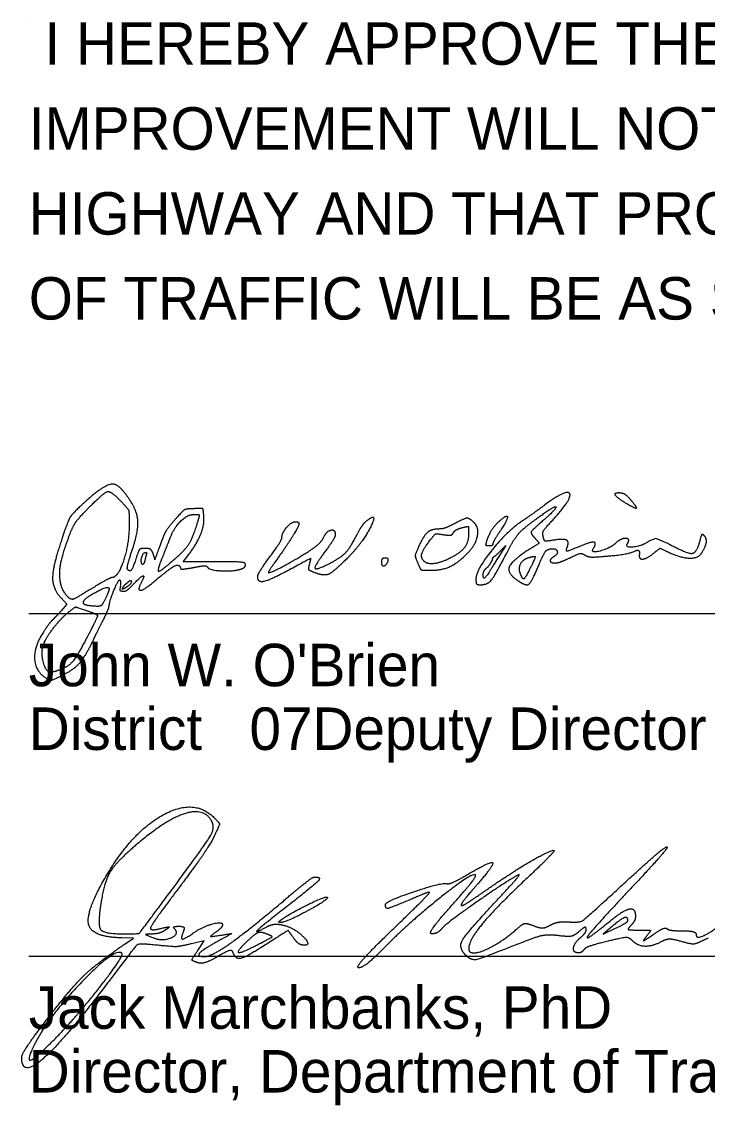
# Model space of a CAD drawing. Extents: x -31.7 to 34, y 0 to 22.
# Drawn here: x 24.504 to 26.767, y 7.305 to 10.877 of the extents above; entities that cross this region are included whole.
import ezdxf

# ---------------------------------------------------------------- set-up
doc = ezdxf.new("R2010")
doc.units = 0
doc.layers.add('SH_Data', color=7, linetype='Continuous')
doc.layers.add('SH_Text', color=7, linetype='Continuous')

msp = doc.modelspace()

# ---------------------------------------------------------------- linework, layer by layer
at = {"layer": 'SH_Data'}
for p, q in [((24.5279, 10.875), (24.5279, 10.875)), ((24.5279, 8.9262), (28.0279, 8.9262)), ((24.5279, 7.7968), (28.0279, 7.7968))]:
    msp.add_line(p, q, dxfattribs=at)
at = {"layer": 'SH_Text'}
for p, q in [((26.4932, 9.2925), (26.4932, 9.2925)), ((24.9902, 8.0019), (24.9902, 8.0019)), ((25.3555, 7.912), (25.3555, 7.912)), ((26.5045, 7.914), (26.5045, 7.914)), ((25.3107, 7.8703), (25.3107, 7.8703)), ((25.7273, 7.883), (25.7273, 7.883))]:
    msp.add_line(p, q, dxfattribs=at)
for points in [[(26.0685, 9.1173), (26.1019, 9.1505), (26.0672, 9.0956)], [(26.636, 9.1565), (26.597, 9.1731), (26.574, 9.1646)], [(25.1404, 9.0966), (25.0375, 9.0966), (25.0558, 9.1206)], [(24.6346, 8.9772), (24.654, 8.9566), (24.6346, 8.9348)], [(26.4527, 7.8943), (26.4232, 7.8687), (26.4638, 7.8884)], [(24.8425, 7.8349), (24.8732, 7.8561), (24.8354, 7.8568)], [(25.0855, 7.8151), (25.1067, 7.8474), (25.0649, 7.8373)]]:
    msp.add_lwpolyline(points, dxfattribs=at)
for points in [[(24.8676, 9.2902), (24.8304, 9.3511), (24.781, 9.3542), (24.7199, 9.2995)], [(24.7219, 9.2706), (24.7758, 9.3259), (24.8, 9.3304), (24.836, 9.2918)], [(26.2529, 9.2302), (26.3225, 9.305), (26.3023, 9.3379), (26.2232, 9.2785)], [(26.4932, 9.2925), (26.467, 9.3085), (26.4588, 9.3248), (26.4772, 9.3244)], [(26.4772, 9.3244), (26.4887, 9.3241), (26.5064, 9.3108), (26.5222, 9.2906)], [(24.7199, 9.2995), (24.6737, 9.2582), (24.656, 9.2292), (24.6319, 9.1557)], [(24.836, 9.2918), (24.8564, 9.2699), (24.8592, 9.261), (24.8592, 9.2177)], [(24.8663, 9.1257), (24.888, 9.1897), (24.8885, 9.2559), (24.8676, 9.2902)], [(26.5222, 9.2906), (26.5367, 9.2722), (26.5254, 9.2729), (26.4932, 9.2925)], [(24.6595, 9.1766), (24.672, 9.2107), (24.69, 9.2379), (24.7219, 9.2706)], [(25.0723, 9.2716), (25.0465, 9.2708), (25.0363, 9.2649), (25.0106, 9.2359)], [(25.1056, 9.2482), (25.1034, 9.271), (25.1012, 9.2725), (25.0723, 9.2716)], [(26.1167, 9.1474), (26.1337, 9.18), (26.1732, 9.218), (26.2332, 9.2597)], [(26.2232, 9.2785), (26.2012, 9.262), (26.1724, 9.2416), (26.1592, 9.2331)], [(26.2332, 9.2597), (26.2688, 9.2843), (26.2661, 9.2682), (26.2292, 9.2362)], [(24.8592, 9.2177), (24.8592, 9.1578), (24.8225, 9.0446), (24.803, 9.0446)], [(25.0106, 9.2359), (24.9936, 9.2167), (24.976, 9.1911), (24.9715, 9.1788)], [(24.9955, 9.1777), (25.008, 9.2099), (25.052, 9.2526), (25.0726, 9.2526)], [(25.0869, 9.2346), (25.0699, 9.1788), (25.0454, 9.1369), (25.013, 9.1083)], [(25.0558, 9.1206), (25.0834, 9.1568), (25.1083, 9.2207), (25.1056, 9.2482)], [(25.0726, 9.2526), (25.0893, 9.2526), (25.0915, 9.2499), (25.0869, 9.2346)], [(25.4192, 9.2214), (25.4192, 9.2136), (25.3786, 9.1487), (25.3398, 9.0946)], [(25.3632, 9.1766), (25.3632, 9.1916), (25.3949, 9.2286), (25.4078, 9.2286)], [(25.4078, 9.2286), (25.4141, 9.2286), (25.4192, 9.2254), (25.4192, 9.2214)], [(25.64, 9.2292), (25.6828, 9.2648), (25.629, 9.1584), (25.5787, 9.1082)], [(25.611, 9.1861), (25.6205, 9.2045), (25.6335, 9.2239), (25.64, 9.2292)], [(25.9291, 9.2206), (25.9127, 9.2118), (25.892, 9.2046), (25.883, 9.2046)], [(25.9977, 9.225), (25.982, 9.2407), (25.9646, 9.2396), (25.9291, 9.2206)], [(25.9786, 9.128), (26.0029, 9.1537), (26.0137, 9.209), (25.9977, 9.225)], [(26.1592, 9.2331), (26.1093, 9.2011), (26.0032, 9.0692), (26.0032, 9.0392)], [(26.0397, 9.1666), (26.0462, 9.1874), (26.0692, 9.2216), (26.0861, 9.2357)], [(26.0861, 9.2357), (26.1081, 9.2539), (26.1061, 9.232), (26.0827, 9.1971)], [(26.2292, 9.2362), (26.1879, 9.2003), (26.1832, 9.1903), (26.1992, 9.1727)], [(26.2252, 9.1794), (26.2222, 9.1911), (26.2302, 9.2057), (26.2529, 9.2302)], [(25.5007, 9.1766), (25.5102, 9.1974), (25.5392, 9.2045), (25.5392, 9.1861)], [(25.5392, 9.1861), (25.5392, 9.1802), (25.5248, 9.1562), (25.5072, 9.1325)], [(25.5203, 9.0912), (25.5584, 9.1108), (25.5884, 9.1422), (25.611, 9.1861)], [(25.883, 9.2046), (25.857, 9.2046), (25.8307, 9.1828), (25.8153, 9.1487)], [(25.8483, 9.1627), (25.8668, 9.187), (25.8727, 9.1898), (25.8962, 9.186)], [(25.8962, 9.186), (25.9142, 9.1831), (25.925, 9.1852), (25.9291, 9.1925)], [(25.9792, 9.1901), (25.9792, 9.1606), (25.9497, 9.1234), (25.9121, 9.1056)], [(25.9291, 9.1925), (25.9325, 9.1985), (25.9451, 9.2058), (25.9572, 9.2088)], [(25.9572, 9.2088), (25.9776, 9.2139), (25.9792, 9.2125), (25.9792, 9.1901)], [(26.0827, 9.1971), (26.0698, 9.1779), (26.0592, 9.1591), (26.0592, 9.1554)], [(26.7567, 9.1824), (26.7506, 9.1884), (26.7465, 9.1842), (26.7424, 9.1678)], [(26.7476, 9.1246), (26.7612, 9.1455), (26.7656, 9.1735), (26.7567, 9.1824)], [(24.6319, 9.1557), (24.6059, 9.0764), (24.607, 9.0067), (24.6346, 8.9772)], [(24.6328, 9.0272), (24.6272, 9.0565), (24.6384, 9.1192), (24.6595, 9.1766)], [(24.9715, 9.1788), (24.9427, 9.1013), (24.9449, 9.105), (24.9381, 9.1235)], [(24.9722, 9.1186), (24.9814, 9.1417), (24.9919, 9.1683), (24.9955, 9.1777)], [(25.3232, 9.1126), (25.3452, 9.1424), (25.3632, 9.1712), (25.3632, 9.1766)], [(25.4494, 9.1297), (25.4726, 9.1445), (25.4957, 9.1656), (25.5007, 9.1766)], [(25.8153, 9.1487), (25.8032, 9.1219), (25.8026, 9.1135), (25.8111, 9.0929)], [(25.8326, 9.0979), (25.8214, 9.1091), (25.828, 9.1361), (25.8483, 9.1627)], [(26.0178, 9.0206), (26.0424, 9.0206), (26.0675, 9.0528), (26.1167, 9.1474)], [(26.0467, 9.1486), (26.0374, 9.1486), (26.0356, 9.1532), (26.0397, 9.1666)], [(26.0592, 9.1554), (26.0592, 9.1517), (26.0536, 9.1486), (26.0467, 9.1486)], [(26.1992, 9.1727), (26.2118, 9.1587), (26.2113, 9.1571), (26.1899, 9.1438)], [(26.2584, 9.1675), (26.2339, 9.1636), (26.2289, 9.1654), (26.2252, 9.1794)], [(26.3044, 9.1449), (26.3116, 9.1636), (26.2926, 9.1729), (26.2584, 9.1675)], [(26.3611, 9.1531), (26.3092, 9.1319), (26.2989, 9.1304), (26.3044, 9.1449)], [(26.3905, 9.1395), (26.4015, 9.1572), (26.3872, 9.1638), (26.3611, 9.1531)], [(26.4648, 9.1583), (26.4453, 9.1401), (26.3809, 9.1238), (26.3905, 9.1395)], [(26.5033, 9.1567), (26.5134, 9.1731), (26.4821, 9.1744), (26.4648, 9.1583)], [(26.574, 9.1646), (26.5525, 9.1482), (26.4941, 9.1419), (26.5033, 9.1567)], [(26.7424, 9.1678), (26.7319, 9.1249), (26.7008, 9.1216), (26.636, 9.1565)], [(24.8545, 9.0707), (24.8517, 9.0735), (24.8571, 9.0982), (24.8663, 9.1257)], [(24.8829, 9.1106), (24.8723, 9.0773), (24.8621, 9.0631), (24.8545, 9.0707)], [(24.9121, 9.1406), (24.8965, 9.1406), (24.8905, 9.1345), (24.8829, 9.1106)], [(24.8992, 9.1001), (24.8992, 9.1043), (24.8998, 9.1099), (24.9062, 9.1246)], [(24.9062, 9.1246), (24.9197, 9.1312), (24.913, 9.1121), (24.9118, 9.1043)], [(24.9381, 9.1235), (24.934, 9.1346), (24.9249, 9.1406), (24.9121, 9.1406)], [(25.013, 9.1083), (24.962, 9.0635), (24.9513, 9.0662), (24.9722, 9.1186)], [(25.2832, 9.0475), (25.2832, 9.0535), (25.3012, 9.0828), (25.3232, 9.1126)], [(25.3196, 9.0606), (25.3278, 9.0606), (25.4081, 9.1033), (25.4494, 9.1297)], [(25.5072, 9.1325), (25.47, 9.0827), (25.4747, 9.0678), (25.5203, 9.0912)], [(25.8552, 9.0686), (25.8926, 9.0686), (25.9478, 9.0952), (25.9786, 9.128)], [(26.0546, 9.0967), (26.0583, 9.1034), (26.059, 9.1122), (26.0685, 9.1173)], [(26.1899, 9.1438), (26.1224, 9.1019), (26.1042, 9.0589), (26.143, 9.0335)], [(26.1499, 9.0571), (26.143, 9.0753), (26.1592, 9.1057), (26.1786, 9.1107)], [(26.1786, 9.1107), (26.1989, 9.1161), (26.1993, 9.1095), (26.1812, 9.0731)], [(26.208, 9.0787), (26.2265, 9.1221), (26.2371, 9.1373), (26.25, 9.1392)], [(26.2592, 9.1126), (26.2466, 9.1048), (26.2499, 9.0926), (26.2647, 9.0926)], [(26.25, 9.1392), (26.2679, 9.1418), (26.2747, 9.1222), (26.2592, 9.1126)], [(26.3138, 9.1099), (26.3413, 9.1232), (26.3526, 9.1251), (26.3634, 9.1184)], [(26.3634, 9.1184), (26.3732, 9.1123), (26.401, 9.1119), (26.4563, 9.1171)], [(26.4563, 9.1171), (26.5084, 9.122), (26.5469, 9.1416), (26.5419, 9.1167)], [(26.5419, 9.1167), (26.5423, 9.1034), (26.5677, 9.1075), (26.59, 9.1251)], [(26.59, 9.1251), (26.6104, 9.1411), (26.6116, 9.1412), (26.6411, 9.1271)], [(26.6411, 9.1271), (26.6784, 9.1093), (26.7368, 9.1079), (26.7476, 9.1246)], [(24.9118, 9.1043), (24.9078, 9.087), (24.8992, 9.0886), (24.8992, 9.1001)], [(24.9324, 9.0243), (24.9663, 9.0529), (25.0264, 9.0971), (25.0295, 9.0718)], [(25.0295, 9.0718), (25.0437, 9.0731), (25.0683, 9.0769), (25.0843, 9.0801)], [(25.0843, 9.0801), (25.1028, 9.0839), (25.1154, 9.0829), (25.1188, 9.0773)], [(25.1188, 9.0773), (25.1245, 9.0681), (25.209, 9.0652), (25.2306, 9.0735)], [(25.2432, 9.0875), (25.2432, 9.0938), (25.2122, 9.0966), (25.1404, 9.0966)], [(25.2306, 9.0735), (25.2375, 9.0761), (25.2432, 9.0824), (25.2432, 9.0875)], [(25.3398, 9.0946), (25.3264, 9.0759), (25.3173, 9.0606), (25.3196, 9.0606)], [(25.4546, 9.0889), (25.4595, 9.1084), (25.4579, 9.108), (25.3928, 9.0728)], [(25.4719, 9.0604), (25.4533, 9.0674), (25.4504, 9.0722), (25.4546, 9.0889)], [(25.5787, 9.1082), (25.5329, 9.0624), (25.5023, 9.0488), (25.4719, 9.0604)], [(25.7039, 9.1086), (25.6969, 9.1086), (25.6912, 9.1029), (25.6912, 9.0959)], [(25.6912, 9.0959), (25.6912, 9.0818), (25.7085, 9.0843), (25.7134, 9.0991)], [(25.7134, 9.0991), (25.7151, 9.1043), (25.7109, 9.1086), (25.7039, 9.1086)], [(25.8111, 9.0929), (25.8201, 9.0712), (25.8248, 9.0686), (25.8552, 9.0686)], [(25.9121, 9.1056), (25.8843, 9.0924), (25.8422, 9.0883), (25.8326, 9.0979)], [(26.0672, 9.0956), (26.041, 9.0516), (26.0272, 9.0373), (26.0272, 9.0539)], [(26.0272, 9.0539), (26.0272, 9.0609), (26.0326, 9.0711), (26.0392, 9.0766)], [(26.0392, 9.0766), (26.0458, 9.0821), (26.0512, 9.0914), (26.0546, 9.0967)], [(26.173, 9.0207), (26.1786, 9.0208), (26.1944, 9.0469), (26.208, 9.0787)], [(26.2647, 9.0926), (26.2721, 9.0926), (26.2942, 9.1004), (26.3138, 9.1099)], [(24.803, 9.0446), (24.7991, 9.0446), (24.7691, 9.0284), (24.7365, 9.0086)], [(24.8708, 9.0202), (24.8973, 9.0478), (24.9119, 9.0524), (24.8995, 9.0291)], [(25.3928, 9.0728), (25.3258, 9.0365), (25.2832, 9.0267), (25.2832, 9.0475)], [(26.0032, 9.0392), (26.0032, 9.0265), (26.0079, 9.0206), (26.0178, 9.0206)], [(26.1812, 9.0731), (26.1659, 9.0423), (26.1573, 9.0379), (26.1499, 9.0571)], [(24.6725, 8.9726), (24.6619, 8.9726), (24.6366, 9.0074), (24.6328, 9.0272)], [(24.7365, 9.0086), (24.7039, 8.9888), (24.6751, 8.9726), (24.6725, 8.9726)], [(24.709, 8.9658), (24.7125, 8.9763), (24.786, 9.0165), (24.7916, 9.0109)], [(24.7916, 9.0109), (24.794, 9.0085), (24.7897, 8.9935), (24.7821, 8.9776)], [(24.792, 8.9444), (24.7951, 8.9734), (24.8361, 9.0628), (24.8283, 9.0021)], [(24.8283, 9.0021), (24.8419, 8.9972), (24.8569, 9.0056), (24.8708, 9.0202)], [(24.8603, 9.02), (24.8459, 9.0093), (24.833, 9.0039), (24.841, 9.0157)], [(24.841, 9.0157), (24.8436, 9.0195), (24.8482, 9.0235), (24.8544, 9.0286)], [(24.8544, 9.0286), (24.8647, 9.0389), (24.8678, 9.028), (24.8603, 9.02)], [(24.8995, 9.0291), (24.886, 9.0038), (24.9047, 9.0011), (24.9324, 9.0243)], [(26.143, 9.0335), (26.1538, 9.0264), (26.1673, 9.0207), (26.173, 9.0207)], [(24.7821, 8.9776), (24.7724, 8.9573), (24.7633, 8.9489), (24.7518, 8.9495)], [(24.6346, 8.9348), (24.624, 8.9229), (24.6112, 8.9094), (24.6063, 8.9048)], [(24.6594, 8.9304), (24.6806, 8.9477), (24.6826, 8.9479), (24.7183, 8.9357)], [(24.7518, 8.9495), (24.7233, 8.9511), (24.7062, 8.9576), (24.709, 8.9658)], [(24.7183, 8.9357), (24.7386, 8.9288), (24.7552, 8.9213), (24.7552, 8.9191)], [(24.7792, 8.9159), (24.7828, 8.921), (24.7859, 8.9315), (24.792, 8.9444)], [(24.5745, 8.8165), (24.5802, 8.8392), (24.631, 8.9073), (24.6594, 8.9304)], [(24.6063, 8.9048), (24.6013, 8.9003), (24.5878, 8.8823), (24.5763, 8.8648)], [(24.7552, 8.9191), (24.7552, 8.9169), (24.7405, 8.8868), (24.7226, 8.8522)], [(24.7491, 8.8553), (24.7618, 8.8822), (24.7762, 8.909), (24.7792, 8.9159)], [(24.5763, 8.8648), (24.5453, 8.8179), (24.5487, 8.7373), (24.5824, 8.7147)], [(24.7226, 8.8522), (24.688, 8.7858), (24.6592, 8.7513), (24.6287, 8.7397)], [(24.6426, 8.7243), (24.6803, 8.7435), (24.7185, 8.7905), (24.7491, 8.8553)], [(24.599, 8.7326), (24.5855, 8.7326), (24.5682, 8.7916), (24.5745, 8.8165)], [(24.5824, 8.7147), (24.5964, 8.7054), (24.6097, 8.7075), (24.6426, 8.7243)], [(24.6287, 8.7397), (24.6185, 8.7358), (24.6052, 8.7326), (24.599, 8.7326)], [(24.7789, 8.0526), (24.8651, 8.203), (25.0732, 8.319), (25.1389, 8.2534)], [(25.1299, 8.2442), (25.104, 8.2862), (24.9779, 8.245), (24.8825, 8.1634)], [(25.1389, 8.2534), (25.1577, 8.2346), (25.1577, 8.2295), (25.1394, 8.1911)], [(24.9902, 8.0019), (25.1115, 8.1653), (25.144, 8.2215), (25.1299, 8.2442)], [(25.1394, 8.1911), (25.1284, 8.1681), (25.0767, 8.0926), (25.0245, 8.0232)], [(24.8825, 8.1634), (24.8159, 8.1064), (24.7771, 8.0423), (24.766, 7.971)], [(26.4869, 8.0315), (26.5619, 8.1006), (26.6279, 8.1572), (26.6336, 8.1573)], [(26.6336, 8.1573), (26.6394, 8.1574), (26.5873, 8.0972), (26.518, 8.0236)], [(26.0326, 8.0111), (26.1131, 8.0677), (26.2445, 8.1449), (26.2602, 8.1449)], [(26.2602, 8.1449), (26.265, 8.1449), (26.2237, 8.1023), (26.1684, 8.0502)], [(25.9736, 8.0646), (26.0524, 8.1108), (26.0646, 8.0975), (26.0054, 8.0302)], [(24.8354, 7.8568), (24.7375, 7.8585), (24.7141, 7.9396), (24.7789, 8.0526)], [(25.369, 7.9791), (25.4194, 8.022), (25.4649, 8.0571), (25.4701, 8.0573)], [(25.4701, 8.0573), (25.495, 8.0578), (25.4716, 8.0322), (25.3857, 7.9649)], [(26.0017, 8.0644), (25.9921, 8.074), (25.7824, 7.907), (25.7045, 7.8278)], [(26.142, 8.0639), (26.0929, 8.0361), (25.9046, 7.9039), (25.8914, 7.888)], [(25.908, 8.0354), (25.9136, 8.0335), (25.9431, 8.0467), (25.9736, 8.0646)], [(25.9239, 7.964), (25.9702, 8.0157), (26.0052, 8.0609), (26.0017, 8.0644)], [(26.1684, 8.0502), (26.0687, 7.9565), (25.9795, 7.8484), (25.9795, 7.8214)], [(26.0768, 7.985), (26.123, 8.0342), (26.1523, 8.0697), (26.142, 8.0639)], [(25.0245, 8.0232), (24.9722, 7.9539), (24.9295, 7.8932), (24.9295, 7.8884)], [(25.7047, 7.9668), (25.7049, 7.9774), (25.8923, 8.0405), (25.908, 8.0354)], [(25.7273, 7.883), (25.7983, 7.9514), (25.8537, 8.0074), (25.8502, 8.0074)], [(25.8502, 8.0074), (25.8468, 8.0074), (25.8178, 7.9962), (25.7857, 7.9824)], [(26.0054, 8.0302), (25.9774, 7.9984), (25.9545, 7.9687), (25.9545, 7.9643)], [(25.9545, 7.9643), (25.9545, 7.9598), (25.9896, 7.9809), (26.0326, 8.0111)], [(26.3119, 7.9091), (26.3453, 7.9063), (26.3688, 7.9227), (26.4869, 8.0315)], [(26.518, 8.0236), (26.3885, 7.8861), (26.3564, 7.8388), (26.4386, 7.9065)], [(24.766, 7.971), (24.7545, 7.8977), (24.776, 7.8699), (24.844, 7.8699)], [(24.844, 7.8699), (24.8907, 7.8699), (24.8953, 7.874), (24.9902, 8.0019)], [(25.1076, 7.7949), (25.1307, 7.7949), (25.2567, 7.8837), (25.369, 7.9791)], [(25.3555, 7.912), (25.3759, 7.9299), (25.5079, 7.9956), (25.5131, 7.9905)], [(25.5131, 7.9905), (25.5193, 7.9843), (25.3767, 7.9074), (25.359, 7.9074)], [(25.7857, 7.9824), (25.7231, 7.9556), (25.7044, 7.952), (25.7047, 7.9668)], [(25.9697, 7.7993), (25.9445, 7.8246), (25.9734, 7.8747), (26.0768, 7.985)], [(26.7295, 7.8684), (26.7295, 7.8456), (26.8248, 7.907), (26.8951, 7.9753)], [(25.3857, 7.9649), (25.2925, 7.8919), (25.271, 7.8704), (25.315, 7.8939)], [(25.8581, 7.8699), (25.8478, 7.8699), (25.8767, 7.9112), (25.9239, 7.964)], [(26.4386, 7.9065), (26.487, 7.9464), (26.5295, 7.9568), (26.5295, 7.9287)], [(25.0736, 7.8743), (25.1025, 7.8941), (25.167, 7.9116), (25.167, 7.8997)], [(25.167, 7.8997), (25.167, 7.8952), (25.1572, 7.8843), (25.1453, 7.8756)], [(25.315, 7.8939), (25.3276, 7.9006), (25.3515, 7.9027), (25.3681, 7.8985)], [(25.359, 7.9074), (25.3542, 7.9074), (25.3526, 7.9095), (25.3555, 7.912)], [(25.3681, 7.8985), (25.4042, 7.8894), (25.4625, 7.8324), (25.4358, 7.8324)], [(26.137, 7.885), (26.1573, 7.903), (26.1701, 7.9056), (26.1939, 7.8966)], [(26.1939, 7.8966), (26.2141, 7.8889), (26.2329, 7.8896), (26.2489, 7.8987)], [(26.2489, 7.8987), (26.2623, 7.9062), (26.2906, 7.9109), (26.3119, 7.9091)], [(26.5045, 7.914), (26.5045, 7.9275), (26.4804, 7.9183), (26.4527, 7.8943)], [(26.4638, 7.8884), (26.4862, 7.8992), (26.5045, 7.9107), (26.5045, 7.914)], [(26.5145, 7.8974), (26.5028, 7.8858), (26.5087, 7.8824), (26.541, 7.8824)], [(26.5295, 7.9287), (26.5295, 7.9198), (26.5227, 7.9057), (26.5145, 7.8974)], [(24.9357, 7.8693), (24.9133, 7.8685), (24.9138, 7.8671), (24.9399, 7.8567)], [(24.9295, 7.8884), (24.9295, 7.8836), (24.9449, 7.8833), (24.9638, 7.8877)], [(24.9795, 7.883), (24.9692, 7.876), (24.9495, 7.8699), (24.9357, 7.8693)], [(24.9399, 7.8567), (24.9698, 7.8447), (25.026, 7.8693), (25.0086, 7.8867)], [(24.9638, 7.8877), (24.9894, 7.8936), (24.9934, 7.8924), (24.9795, 7.883)], [(25.0086, 7.8867), (25.004, 7.8912), (25.0103, 7.8949), (25.0225, 7.8949)], [(25.0225, 7.8949), (25.037, 7.8949), (25.0422, 7.8885), (25.0375, 7.8762)], [(25.0375, 7.8762), (25.0285, 7.8529), (25.0414, 7.8523), (25.0736, 7.8743)], [(25.1453, 7.8756), (25.1264, 7.8618), (25.1284, 7.8605), (25.161, 7.8654)], [(25.161, 7.8654), (25.1977, 7.871), (25.1976, 7.8707), (25.1522, 7.8456)], [(25.3107, 7.8703), (25.2935, 7.8767), (25.277, 7.8716), (25.2576, 7.8538)], [(25.2826, 7.834), (25.329, 7.8577), (25.3325, 7.8623), (25.3107, 7.8703)], [(25.4011, 7.8571), (25.3843, 7.8812), (25.3822, 7.8807), (25.3165, 7.8384)], [(25.617, 7.7581), (25.6067, 7.7583), (25.6563, 7.8145), (25.7273, 7.883)], [(25.8914, 7.888), (25.8831, 7.878), (25.8682, 7.8699), (25.8581, 7.8699)], [(25.9975, 7.8074), (26.0192, 7.8074), (26.1006, 7.8527), (26.137, 7.885)], [(26.2749, 7.864), (26.2457, 7.8677), (26.2058, 7.8612), (26.1693, 7.8468)], [(26.3444, 7.8784), (26.3287, 7.8642), (26.3075, 7.8598), (26.2749, 7.864)], [(26.367, 7.8859), (26.367, 7.893), (26.3568, 7.8896), (26.3444, 7.8784)], [(26.3482, 7.8574), (26.3585, 7.866), (26.367, 7.8788), (26.367, 7.8859)], [(26.541, 7.8824), (26.5785, 7.8824), (26.5809, 7.8804), (26.5654, 7.8611)], [(26.5654, 7.8611), (26.5533, 7.8461), (26.5598, 7.8478), (26.5871, 7.8669)], [(26.5871, 7.8669), (26.6085, 7.8819), (26.6293, 7.891), (26.6332, 7.8871)], [(26.6332, 7.8871), (26.6371, 7.8831), (26.6604, 7.8799), (26.6849, 7.8799)], [(26.6849, 7.8799), (26.7094, 7.8799), (26.7295, 7.8748), (26.7295, 7.8684)], [(24.5916, 7.5927), (24.6692, 7.6932), (24.7493, 7.7705), (24.8425, 7.8349)], [(24.9237, 7.835), (24.8903, 7.8383), (24.8786, 7.8278), (24.8019, 7.7262)], [(25.0649, 7.8373), (25.0246, 7.8276), (25.0023, 7.8272), (24.9237, 7.835)], [(25.1522, 7.8456), (25.1011, 7.8174), (25.0814, 7.7949), (25.1076, 7.7949)], [(25.3165, 7.8384), (25.2476, 7.794), (25.2101, 7.7843), (25.202, 7.8086)], [(25.2576, 7.8538), (25.2133, 7.8133), (25.2246, 7.8044), (25.2826, 7.834)], [(25.4358, 7.8324), (25.4262, 7.8324), (25.4106, 7.8435), (25.4011, 7.8571)], [(25.7045, 7.8278), (25.6667, 7.7893), (25.6273, 7.7579), (25.617, 7.7581)], [(26.1693, 7.8468), (26.0233, 7.7891), (25.9882, 7.7808), (25.9697, 7.7993)], [(26.3412, 7.8074), (26.3229, 7.8074), (26.3274, 7.8402), (26.3482, 7.8574)], [(26.4355, 7.8449), (26.3972, 7.8357), (26.3629, 7.8235), (26.3594, 7.8178)], [(26.5199, 7.847), (26.5088, 7.8582), (26.4887, 7.8577), (26.4355, 7.8449)], [(26.6162, 7.8445), (26.5854, 7.8281), (26.5376, 7.8293), (26.5199, 7.847)], [(26.6807, 7.8446), (26.6538, 7.8523), (26.6307, 7.8523), (26.6162, 7.8445)], [(26.7698, 7.8559), (26.7324, 7.8374), (26.7138, 7.8351), (26.6807, 7.8446)], [(24.8354, 7.8057), (24.8145, 7.8266), (24.596, 7.6009), (24.5497, 7.5106)], [(24.6198, 7.5293), (24.6874, 7.5984), (24.8431, 7.798), (24.8354, 7.8057)], [(25.0843, 7.775), (25.0661, 7.782), (25.0662, 7.7856), (25.0855, 7.8151)], [(25.1508, 7.7948), (25.1252, 7.7797), (25.0953, 7.7708), (25.0843, 7.775)], [(25.202, 7.8086), (25.1991, 7.8172), (25.1799, 7.812), (25.1508, 7.7948)], [(25.9795, 7.8214), (25.9795, 7.8137), (25.9876, 7.8074), (25.9975, 7.8074)], [(26.3594, 7.8178), (26.3559, 7.8121), (26.3477, 7.8074), (26.3412, 7.8074)], [(24.8019, 7.7262), (24.6496, 7.5241), (24.5045, 7.3955), (24.5045, 7.4625)], [(24.5045, 7.4625), (24.5045, 7.4721), (24.5437, 7.5307), (24.5916, 7.5927)], [(24.5497, 7.5106), (24.5184, 7.4496), (24.55, 7.4581), (24.6198, 7.5293)]]:
    msp.add_open_spline(points, degree=2, dxfattribs=at)

# ---------------------------------------------------------------- texts
at = {"layer": 'SH_Data'}
for s, p in [(' I HEREBY APPROVE THESE PLANS AND DECLARE THAT THE MAKING OF THIS', (24.5279, 10.735)), ('IMPROVEMENT WILL NOT REQUIRE THE CLOSING TO TRAFFIC OF THE', (24.5279, 10.455)), ('HIGHWAY AND THAT PROVISIONS FOR THE MAINTENANCE AND SAFETY', (24.5279, 10.175)), ('OF TRAFFIC WILL BE AS SET FORTH ON THE PLANS AND ESTIMATES.', (24.5279, 9.895))]:
    msp.add_text(s, height=0.14, dxfattribs=at).set_placement(p)
at = {"layer": 'SH_Text'}
for s, p in [("John W. O'Brien", (24.5279, 8.6862)), ('District       Deputy Director', (24.5279, 8.4762)), ('              07', (24.5279, 8.4762)), ('Jack Marchbanks, PhD', (24.5279, 7.5568)), ('Director, Department of Transportation', (24.5279, 7.3468))]:
    msp.add_text(s, height=0.14, dxfattribs=at).set_placement(p)

doc.saveas('drawing.dxf')
